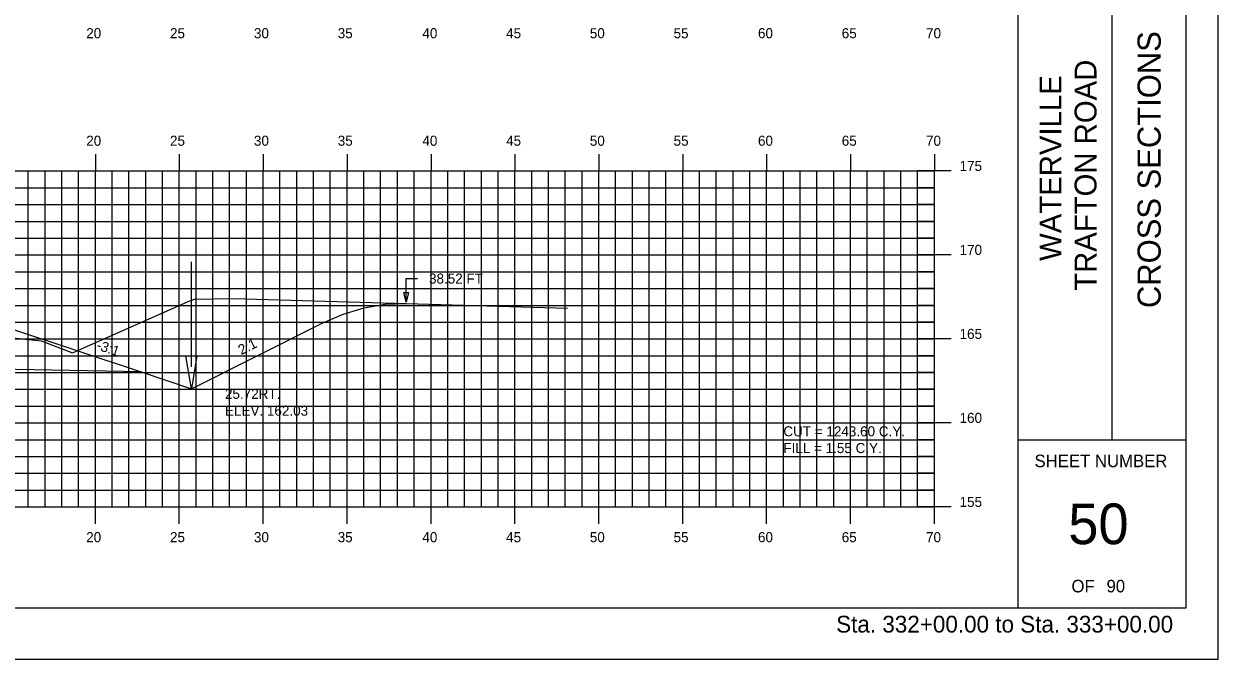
# Model space of a CAD drawing. Extents: x 1141646 to 1141816, y 608981 to 609091.
# Drawn here: x 1141744.8 to 1141815.9, y 608981.3 to 609019.1 of the extents above; entities that cross this region are included whole.
import ezdxf

# ---------------------------------------------------------------- set-up
doc = ezdxf.new("R2010")
doc.units = 0
for name, color, linetype in [('ANNOTATION', 7, 'Continuous'), ('BORDER', 7, 'Continuous'), ('D_Drainage_Ditch_Line', 7, 'Continuous'), ('D_Roadway_SlopeLines', 7, 'Continuous'), ('D_Roadway_SubGrade', 7, 'Continuous'), ('D_Text_Standard', 7, 'Continuous'), ('H_V ANNOTATION', 7, 'Continuous'), ('HIGHWAY_TITLE', 7, 'Continuous'), ('MAJOR', 7, 'Continuous'), ('MINOR', 7, 'Continuous'), ('PLOT BOUNDARY', 7, 'Continuous'), ('S_Roadway_Centerline', 7, 'Continuous')]:
    doc.layers.add(name, color=color, linetype=linetype)

msp = doc.modelspace()

# ---------------------------------------------------------------- linework, layer by layer
msp.add_lwpolyline([(1141686.671, 609003.648), (1141687.921, 609003.524), (1141689.171, 609003.256), (1141690.421, 609002.846), (1141691.671, 609002.292), (1141701.588, 608997.333), (1141704.588, 608998.333), (1141712.195, 609000.869), (1141712.196, 609000.869), (1141718.027, 609001.102), (1141729.027, 609001.322), (1141740.027, 609001.102), (1141744.027, 609000.942), (1141751.751, 608998.368), (1141754.751, 608997.368), (1141762.545, 609001.265), (1141763.795, 609001.808), (1141765.045, 609002.185), (1141766.295, 609002.397), (1141767.545, 609002.444)])
at = {"layer": 'BORDER'}
for p, q in [((1141804.027, 608984.335), (1141804.027, 609089.335)), ((1141809.618, 608994.338), (1141809.618, 609029.338)), ((1141804.027, 608994.338), (1141814.027, 608994.338))]:
    msp.add_line(p, q, dxfattribs=at)
msp.add_lwpolyline([(1141654.027, 608984.335), (1141814.027, 608984.335), (1141814.027, 609089.335), (1141654.027, 609089.335)], close=True, dxfattribs=at)
at = {"layer": 'D_Drainage_Ditch_Line'}
msp.add_line((1141754.751, 608998.68), (1141754.751, 609004.924), dxfattribs=at)
msp.add_line((1141754.751, 608998.68), (1141754.751, 609004.924), dxfattribs=at)
msp.add_lwpolyline([(1141754.423, 608999.336), (1141755.079, 608999.336), (1141754.751, 608997.368)], close=True, dxfattribs=at)
msp.add_lwpolyline([(1141754.423, 608999.336), (1141755.079, 608999.336), (1141754.751, 608997.368)], close=True, dxfattribs=at)
at = {"layer": 'D_Roadway_SlopeLines'}
for points in [[(1141754.751, 608997.368), (1141762.545, 609001.265), (1141763.795, 609001.808), (1141765.045, 609002.185), (1141766.295, 609002.397), (1141767.545, 609002.444)], [(1141751.751, 608998.368), (1141754.751, 608997.368)]]:
    msp.add_lwpolyline(points, dxfattribs=at)
at = {"layer": 'D_Roadway_SubGrade'}
msp.add_lwpolyline([(1141740.027, 609000.686), (1141740.027, 609000.852), (1141744.027, 609000.692), (1141744.027, 609000.942), (1141744.027, 609000.942), (1141751.751, 608998.368), (1141740.027, 608998.602)], close=True, dxfattribs=at)
at = {"layer": 'D_Text_Standard'}
msp.add_lwpolyline([(1141767.545, 609002.515), (1141767.55, 609003.928), (1141768.23, 609003.928)], dxfattribs=at)
msp.add_lwpolyline([(1141767.545, 609002.515), (1141767.402, 609003.098), (1141767.693, 609003.097)], close=True, dxfattribs=at)
at = {"layer": 'MAJOR'}
for p, q in [((1141749.027, 609011.337), (1141749.027, 609010.335)), ((1141754.027, 609011.337), (1141754.027, 609010.335)), ((1141759.027, 609011.337), (1141759.027, 609010.335)), ((1141764.027, 609011.337), (1141764.027, 609010.335)), ((1141769.027, 609011.337), (1141769.027, 609010.335)), ((1141774.027, 609011.337), (1141774.027, 609010.335)), ((1141779.027, 609011.337), (1141779.027, 609010.335)), ((1141784.027, 609011.337), (1141784.027, 609010.335)), ((1141789.027, 609011.337), (1141789.027, 609010.335)), ((1141794.027, 609011.337), (1141794.027, 609010.335)), ((1141799.027, 609011.337), (1141799.027, 609010.335)), ((1141659.027, 609010.335), (1141799.027, 609010.335)), ((1141659.027, 609010.335), (1141799.027, 609010.335)), ((1141749.027, 608990.335), (1141749.027, 609010.335)), ((1141754.027, 608990.335), (1141754.027, 609010.335)), ((1141759.027, 608990.335), (1141759.027, 609010.335)), ((1141764.027, 608990.335), (1141764.027, 609010.335)), ((1141769.027, 608990.335), (1141769.027, 609010.335)), ((1141774.027, 608990.335), (1141774.027, 609010.335)), ((1141779.027, 608990.335), (1141779.027, 609010.335)), ((1141784.027, 608990.335), (1141784.027, 609010.335)), ((1141789.027, 608990.335), (1141789.027, 609010.335)), ((1141794.027, 608990.335), (1141794.027, 609010.335)), ((1141800.029, 609010.335), (1141798.025, 609010.335)), ((1141799.027, 608990.335), (1141799.027, 609010.335)), ((1141799.027, 608990.335), (1141799.027, 609010.335)), ((1141659.027, 609005.335), (1141799.027, 609005.335)), ((1141800.029, 609005.335), (1141798.025, 609005.335)), ((1141659.027, 609000.335), (1141799.027, 609000.335)), ((1141800.029, 609000.335), (1141798.025, 609000.335)), ((1141659.027, 608995.335), (1141799.027, 608995.335)), ((1141800.029, 608995.335), (1141798.025, 608995.335)), ((1141659.027, 608990.335), (1141799.027, 608990.335)), ((1141659.027, 608990.335), (1141799.027, 608990.335)), ((1141749.027, 608989.333), (1141749.027, 608990.335)), ((1141754.027, 608989.333), (1141754.027, 608990.335)), ((1141759.027, 608989.333), (1141759.027, 608990.335)), ((1141764.027, 608989.333), (1141764.027, 608990.335)), ((1141769.027, 608989.333), (1141769.027, 608990.335)), ((1141774.027, 608989.333), (1141774.027, 608990.335)), ((1141779.027, 608989.333), (1141779.027, 608990.335)), ((1141784.027, 608989.333), (1141784.027, 608990.335)), ((1141789.027, 608989.333), (1141789.027, 608990.335)), ((1141794.027, 608989.333), (1141794.027, 608990.335)), ((1141800.029, 608990.335), (1141798.025, 608990.335)), ((1141799.027, 608989.333), (1141799.027, 608990.335))]:
    msp.add_line(p, q, dxfattribs=at)
at = {"layer": 'MINOR'}
for p, q in [((1141745.027, 608990.335), (1141745.027, 609010.335)), ((1141746.027, 608990.335), (1141746.027, 609010.335)), ((1141747.027, 608990.335), (1141747.027, 609010.335)), ((1141748.027, 608990.335), (1141748.027, 609010.335)), ((1141750.027, 608990.335), (1141750.027, 609010.335)), ((1141751.027, 608990.335), (1141751.027, 609010.335)), ((1141752.027, 608990.335), (1141752.027, 609010.335)), ((1141753.027, 608990.335), (1141753.027, 609010.335)), ((1141755.027, 608990.335), (1141755.027, 609010.335)), ((1141756.027, 608990.335), (1141756.027, 609010.335)), ((1141757.027, 608990.335), (1141757.027, 609010.335)), ((1141758.027, 608990.335), (1141758.027, 609010.335)), ((1141760.027, 608990.335), (1141760.027, 609010.335)), ((1141761.027, 608990.335), (1141761.027, 609010.335)), ((1141762.027, 608990.335), (1141762.027, 609010.335)), ((1141763.027, 608990.335), (1141763.027, 609010.335)), ((1141765.027, 608990.335), (1141765.027, 609010.335)), ((1141766.027, 608990.335), (1141766.027, 609010.335)), ((1141767.027, 608990.335), (1141767.027, 609010.335)), ((1141768.027, 608990.335), (1141768.027, 609010.335)), ((1141770.027, 608990.335), (1141770.027, 609010.335)), ((1141771.027, 608990.335), (1141771.027, 609010.335)), ((1141772.027, 608990.335), (1141772.027, 609010.335)), ((1141773.027, 608990.335), (1141773.027, 609010.335)), ((1141775.027, 608990.335), (1141775.027, 609010.335)), ((1141776.027, 608990.335), (1141776.027, 609010.335)), ((1141777.027, 608990.335), (1141777.027, 609010.335)), ((1141778.027, 608990.335), (1141778.027, 609010.335)), ((1141780.027, 608990.335), (1141780.027, 609010.335)), ((1141781.027, 608990.335), (1141781.027, 609010.335)), ((1141782.027, 608990.335), (1141782.027, 609010.335)), ((1141783.027, 608990.335), (1141783.027, 609010.335)), ((1141785.027, 608990.335), (1141785.027, 609010.335)), ((1141786.027, 608990.335), (1141786.027, 609010.335)), ((1141787.027, 608990.335), (1141787.027, 609010.335)), ((1141788.027, 608990.335), (1141788.027, 609010.335)), ((1141790.027, 608990.335), (1141790.027, 609010.335)), ((1141791.027, 608990.335), (1141791.027, 609010.335)), ((1141792.027, 608990.335), (1141792.027, 609010.335)), ((1141793.027, 608990.335), (1141793.027, 609010.335)), ((1141795.027, 608990.335), (1141795.027, 609010.335)), ((1141796.027, 608990.335), (1141796.027, 609010.335)), ((1141797.027, 608990.335), (1141797.027, 609010.335)), ((1141798.027, 608990.335), (1141798.027, 609010.335)), ((1141659.027, 609009.335), (1141799.027, 609009.335)), ((1141799.027, 609009.335), (1141798.025, 609009.335)), ((1141659.027, 609008.335), (1141799.027, 609008.335)), ((1141799.027, 609008.335), (1141798.025, 609008.335)), ((1141659.027, 609007.335), (1141799.027, 609007.335)), ((1141799.027, 609007.335), (1141798.025, 609007.335)), ((1141659.027, 609006.335), (1141799.027, 609006.335)), ((1141799.027, 609006.335), (1141798.025, 609006.335)), ((1141659.027, 609004.335), (1141799.027, 609004.335)), ((1141799.027, 609004.335), (1141798.025, 609004.335)), ((1141659.027, 609003.335), (1141799.027, 609003.335)), ((1141799.027, 609003.335), (1141798.025, 609003.335)), ((1141659.027, 609002.335), (1141799.027, 609002.335)), ((1141799.027, 609002.335), (1141798.025, 609002.335)), ((1141659.027, 609001.335), (1141799.027, 609001.335)), ((1141799.027, 609001.335), (1141798.025, 609001.335)), ((1141659.027, 608999.335), (1141799.027, 608999.335)), ((1141799.027, 608999.335), (1141798.025, 608999.335)), ((1141659.027, 608998.335), (1141799.027, 608998.335)), ((1141799.027, 608998.335), (1141798.025, 608998.335)), ((1141659.027, 608997.335), (1141799.027, 608997.335)), ((1141799.027, 608997.335), (1141798.025, 608997.335)), ((1141659.027, 608996.335), (1141799.027, 608996.335)), ((1141799.027, 608996.335), (1141798.025, 608996.335)), ((1141659.027, 608994.335), (1141799.027, 608994.335)), ((1141799.027, 608994.335), (1141798.025, 608994.335)), ((1141659.027, 608993.335), (1141799.027, 608993.335)), ((1141799.027, 608993.335), (1141798.025, 608993.335)), ((1141659.027, 608992.335), (1141799.027, 608992.335)), ((1141799.027, 608992.335), (1141798.025, 608992.335)), ((1141659.027, 608991.335), (1141799.027, 608991.335)), ((1141799.027, 608991.335), (1141798.025, 608991.335))]:
    msp.add_line(p, q, dxfattribs=at)
at = {"layer": 'PLOT BOUNDARY'}
msp.add_lwpolyline([(1141645.934, 608981.276), (1141815.934, 608981.276), (1141815.934, 609091.276), (1141645.934, 609091.276)], close=True, dxfattribs=at)
at = {"layer": 'S_Roadway_Centerline'}
msp.add_lwpolyline([(1141676.132, 609003.905), (1141676.422, 609003.981), (1141681.475, 609003.868), (1141704.424, 609002.897), (1141713.381, 608999.604), (1141713.764, 608999.466), (1141716.715, 609000.383), (1141716.794, 609000.403), (1141716.895, 609000.414), (1141720.259, 609000.712), (1141730.384, 609000.959), (1141731.148, 609000.975), (1141741.378, 609000.622), (1141742.175, 609000.6), (1141742.437, 609000.576), (1141745.801, 609000.225), (1141745.956, 609000.162), (1141747.669, 608999.515), (1141754.519, 609002.541), (1141754.929, 609002.699), (1141757.261, 609002.735), (1141777.166, 609002.172)], dxfattribs=at)

# ---------------------------------------------------------------- texts
at = {"layer": 'ANNOTATION'}
for s, rotation, p in [('-3:1', 341.56521, (1141749.039, 608999.726)), ('2:1', 26.56505, (1141757.721, 608999.371))]:
    msp.add_text(s, height=0.6, rotation=rotation, dxfattribs=at).set_placement(p)
at = {"layer": 'BORDER'}
msp.add_text('CROSS SECTIONS', height=1.37787, rotation=90, dxfattribs=at).set_placement((1141812.512, 609002.172))
for s, height, p in [('SHEET NUMBER', 0.74527, (1141804.993, 608992.701)), ('50', 2.4194, (1141807.003, 608988.118)), ('OF', 0.7453, (1141807.194, 608985.248)), ('90', 0.7453, (1141809.284, 608985.248))]:
    msp.add_text(s, height=height, dxfattribs=at).set_placement(p)
at = {"layer": 'D_Text_Standard'}
for s, p in [('38.52 FT', (1141768.91, 609003.628)), ('25.72', (1141756.751, 608996.768)), ('25.72RT.', (1141756.751, 608996.768)), ('ELEV. 162.03', (1141756.751, 608995.766)), ('ELEV. 162.03', (1141756.751, 608995.766)), ('CUT = 1243.60 C.Y.', (1141790.027, 608994.535)), ('FILL = 1.55 C.Y.', (1141790.027, 608993.539))]:
    msp.add_text(s, height=0.6, dxfattribs=at).set_placement(p)
at = {"layer": 'H_V ANNOTATION'}
for s, height, p in [('20', 0.6, (1141748.481, 609018.235)), ('25', 0.6, (1141753.473, 609018.235)), ('30', 0.6, (1141758.476, 609018.235)), ('35', 0.6, (1141763.468, 609018.235)), ('40', 0.6, (1141768.513, 609018.235)), ('45', 0.6, (1141773.505, 609018.235)), ('50', 0.6, (1141778.492, 609018.235)), ('55', 0.6, (1141783.484, 609018.235)), ('60', 0.6, (1141788.513, 609018.235)), ('65', 0.6, (1141793.505, 609018.235)), ('70', 0.6, (1141798.529, 609018.235)), ('20', 0.6, (1141748.481, 609011.835)), ('25', 0.6, (1141753.473, 609011.835)), ('30', 0.6, (1141758.476, 609011.835)), ('35', 0.6, (1141763.468, 609011.835)), ('40', 0.6, (1141768.513, 609011.835)), ('45', 0.6, (1141773.505, 609011.835)), ('50', 0.6, (1141778.492, 609011.835)), ('55', 0.6, (1141783.484, 609011.835)), ('60', 0.6, (1141788.513, 609011.835)), ('65', 0.6, (1141793.505, 609011.835)), ('70', 0.6, (1141798.529, 609011.835)), ('175', 0.6, (1141800.527, 609010.335)), ('170', 0.6, (1141800.527, 609005.335)), ('165', 0.6, (1141800.527, 609000.335)), ('160', 0.6, (1141800.527, 608995.335)), ('155', 0.6, (1141800.527, 608990.335)), ('20', 0.6, (1141748.481, 608988.235)), ('25', 0.6, (1141753.473, 608988.235)), ('30', 0.6, (1141758.476, 608988.235)), ('35', 0.6, (1141763.468, 608988.235)), ('40', 0.6, (1141768.513, 608988.235)), ('45', 0.6, (1141773.505, 608988.235)), ('50', 0.6, (1141778.492, 608988.235)), ('55', 0.6, (1141783.484, 608988.235)), ('60', 0.6, (1141788.513, 608988.235)), ('65', 0.6, (1141793.505, 608988.235)), ('70', 0.6, (1141798.529, 608988.235)), ('Sta. 332+00.00 to Sta. 333+00.00', 1.0002, (1141793.173, 608982.855))]:
    msp.add_text(s, height=height, dxfattribs=at).set_placement(p)
at = {"layer": 'HIGHWAY_TITLE'}
for s, height, p in [('TRAFTON ROAD', 1.30428, (1141808.687, 609003.201)), ('WATERVILLE', 1.3043, (1141806.6, 609004.98))]:
    msp.add_text(s, height=height, rotation=90, dxfattribs=at).set_placement(p)

doc.saveas('drawing.dxf')
